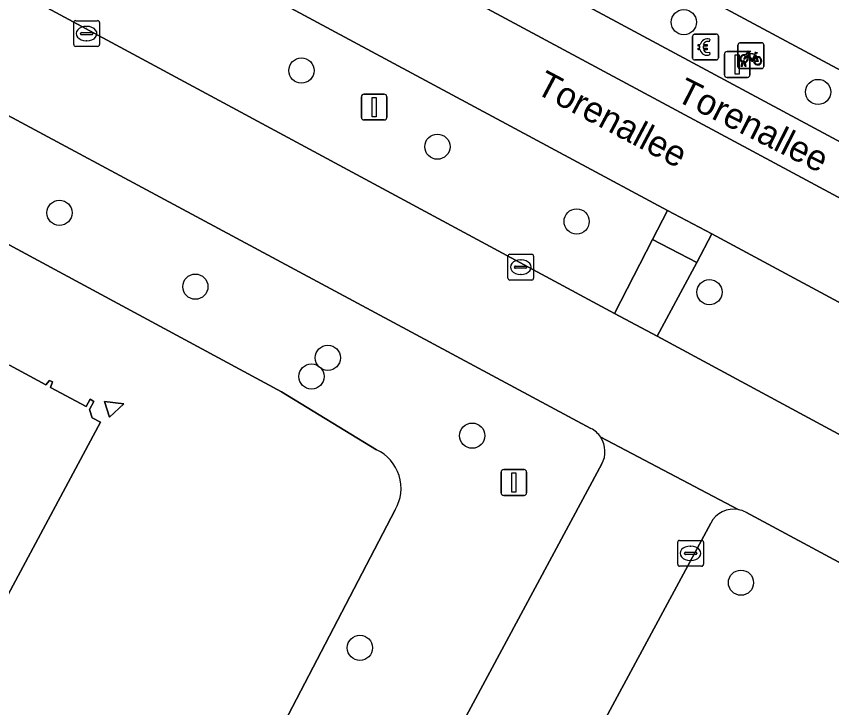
# Model space of a CAD drawing. Extents: x 159489 to 160304, y 383825 to 384531.
# Drawn here: x 159914.43 to 159946.05, y 384116.4 to 384143.23 of the extents above; entities that cross this region are included whole.
import ezdxf

# ---------------------------------------------------------------- set-up
doc = ezdxf.new("R2010")
doc.units = 0
for name, color, linetype in [('IMGEO_Betaalautomaat', 7, 'Continuous'), ('IMGEO_Boom', 7, 'Continuous'), ('IMGEO_Fietsenrek', 7, 'Continuous'), ('IMGEO_Groenvoorziening', 7, 'Continuous'), ('IMGEO_Kolk', 7, 'Continuous'), ('IMGEO_Lichtmast', 7, 'Continuous'), ('IMGEO_Openbare_ruimte_label', 7, 'Continuous'), ('IMGEO_Pand', 7, 'Continuous'), ('IMGEO_Parkeervlak_gesloten', 7, 'Continuous'), ('IMGEO_Rijbaan_lokaal_gesloten', 7, 'Continuous'), ('IMGEO_Voetgangersgebied_gesloten', 7, 'Continuous'), ('IMGEO_Voetpad_gesloten', 7, 'Continuous'), ('IMGEO_Voetpad_open', 7, 'Continuous')]:
    doc.layers.add(name, color=color, linetype=linetype)

msp = doc.modelspace()

# ---------------------------------------------------------------- linework, layer by layer
at = {"layer": 'IMGEO_Betaalautomaat'}
for p, q in [((159940.662, 384141.609), (159940.662, 384142.45)), ((159940.662, 384142.45), (159940.662, 384141.609)), ((159940.737, 384142.533), (159941.578, 384142.533)), ((159941.578, 384142.533), (159940.737, 384142.533)), ((159941.324, 384142.338), (159941.307, 384142.238)), ((159941.661, 384142.459), (159941.661, 384141.618)), ((159941.661, 384141.618), (159941.661, 384142.459)), ((159940.945, 384141.997), (159940.945, 384142.065)), ((159941.066, 384142.065), (159941.066, 384141.997)), ((159941.311, 384141.832), (159941.333, 384141.745)), ((159941.587, 384141.534), (159940.746, 384141.534)), ((159940.746, 384141.534), (159941.587, 384141.534))]:
    msp.add_line(p, q, dxfattribs=at)
for points in [[(159940.945, 384142.065), (159940.876, 384142.065), (159940.876, 384142.134), (159940.955, 384142.134)], [(159940.95, 384141.928), (159940.876, 384141.928), (159940.876, 384141.997), (159940.945, 384141.997)], [(159941.077, 384142.134), (159941.224, 384142.134), (159941.224, 384142.065), (159941.066, 384142.065)], [(159941.066, 384141.997), (159941.224, 384141.997), (159941.224, 384141.928), (159941.08, 384141.928)]]:
    msp.add_lwpolyline(points, dxfattribs=at)
for centre, radius, start, end in [((159940.74, 384142.456), 0.0779, 92.4484, 184.2845), ((159940.74, 384142.456), 0.0779, 92.4484, 184.2845), ((159941.238, 384142.058), 0.293, 73.014, 165.0139), ((159941.584, 384142.456), 0.0779, 2.4484, 94.2845), ((159941.584, 384142.456), 0.0779, 2.4484, 94.2845), ((159941.244, 384142.071), 0.179, 69.3236, 159.5683), ((159941.211, 384141.983), 0.267, 191.8096, 297.0389), ((159941.244, 384141.998), 0.179, 202.7625, 291.8693), ((159940.74, 384141.612), 0.0779, 182.4484, 274.2845), ((159940.74, 384141.612), 0.0779, 182.4484, 274.2845), ((159941.584, 384141.612), 0.0779, 272.4484, 4.2845), ((159941.584, 384141.612), 0.0779, 272.4484, 4.2845)]:
    msp.add_arc(centre, radius, start, end, dxfattribs=at)
at = {"layer": 'IMGEO_Boom'}
for centre in [(159940.319, 384143.002), (159925.488, 384141.122), (159945.528, 384140.293), (159930.762, 384138.168), (159916.103, 384135.603), (159936.162, 384135.269), (159921.375, 384132.738), (159941.314, 384132.524), (159926.512, 384129.976), (159925.878, 384129.253), (159932.113, 384126.957), (159942.536, 384121.253), (159927.757, 384118.726)]:
    msp.add_circle(centre, 0.489, dxfattribs=at)
at = {"layer": 'IMGEO_Fietsenrek'}
for p, q in [((159942.417, 384141.273), (159942.417, 384142.114)), ((159942.417, 384142.114), (159942.417, 384141.273)), ((159942.492, 384142.198), (159943.333, 384142.198)), ((159943.333, 384142.198), (159942.492, 384142.198)), ((159943.417, 384142.123), (159943.417, 384141.282)), ((159943.417, 384141.282), (159943.417, 384142.123)), ((159943.104, 384141.747), (159943.14, 384141.652)), ((159942.544, 384141.282), (159942.583, 384141.442)), ((159942.613, 384141.43), (159942.578, 384141.282)), ((159942.655, 384141.454), (159942.654, 384141.458)), ((159942.696, 384141.282), (159942.662, 384141.424)), ((159942.686, 384141.465), (159942.687, 384141.458)), ((159942.694, 384141.428), (159942.729, 384141.282)), ((159943.342, 384141.198), (159942.501, 384141.198)), ((159942.501, 384141.198), (159943.342, 384141.198)), ((159942.578, 384141.282), (159942.544, 384141.282)), ((159942.729, 384141.282), (159942.696, 384141.282))]:
    msp.add_line(p, q, dxfattribs=at)
for points in [[(159942.751, 384141.672), (159942.699, 384141.582), (159942.659, 384141.557), (159942.66, 384141.604), (159942.715, 384141.698)], [(159942.73, 384141.724), (159942.825, 384141.888), (159942.911, 384141.874), (159942.913, 384141.865), (159942.857, 384141.854), (159942.83, 384141.809), (159943.086, 384141.768)], [(159943.026, 384141.48), (159942.976, 384141.48), (159942.785, 384141.731), (159942.766, 384141.699)], [(159943.073, 384141.743), (159942.816, 384141.784), (159942.799, 384141.755), (159942.966, 384141.535), (159943.073, 384141.743)], [(159943.121, 384141.645), (159943.091, 384141.722), (159942.982, 384141.504), (159943.025, 384141.504)], [(159943.086, 384141.768), (159943.111, 384141.817), (159943.105, 384141.821), (159943.082, 384141.825), (159943.07, 384141.832), (159943.069, 384141.835), (159943.071, 384141.84), (159943.166, 384141.825), (159943.168, 384141.815), (159943.158, 384141.802), (159943.146, 384141.796), (159943.132, 384141.802), (159943.104, 384141.747)], [(159943.055, 384141.504), (159943.175, 384141.503), (159943.131, 384141.617)], [(159943.151, 384141.624), (159943.206, 384141.479), (159943.056, 384141.479)]]:
    msp.add_lwpolyline(points, dxfattribs=at)
for centre, radius, start, end in [((159942.495, 384142.12), 0.0779, 92.4484, 184.2845), ((159942.495, 384142.12), 0.0779, 92.4484, 184.2845), ((159943.339, 384142.12), 0.0779, 2.4484, 94.2845), ((159943.339, 384142.12), 0.0779, 2.4484, 94.2845), ((159942.657, 384141.583), 0.159, 62.6766, 242.1369), ((159942.657, 384141.583), 0.129, 63.3192, 238.903), ((159942.657, 384141.583), 0.129, 283.6043, 43.4302), ((159942.657, 384141.583), 0.159, 283.5766, 46.6042), ((159942.637, 384141.454), 0.0499, 12.8025, 158.6934), ((159942.657, 384141.583), 0.159, 253.9967, 271.7867), ((159942.637, 384141.454), 0.0174, 12.8025, 163.4502), ((159942.657, 384141.583), 0.129, 253.415, 269.0204), ((159943.184, 384141.499), 0.159, 113.3408, 178.3217), ((159943.184, 384141.499), 0.159, 187.0065, 105.7708), ((159943.184, 384141.499), 0.129, 113.923, 177.9556), ((159943.184, 384141.499), 0.129, 188.6715, 104.5883), ((159942.495, 384141.276), 0.0779, 182.4484, 274.2845), ((159942.495, 384141.276), 0.0779, 182.4484, 274.2845), ((159943.339, 384141.276), 0.0779, 272.4484, 4.2845), ((159943.339, 384141.276), 0.0779, 272.4484, 4.2845)]:
    msp.add_arc(centre, radius, start, end, dxfattribs=at)
at = {"layer": 'IMGEO_Groenvoorziening'}
for points in [[(159899.78, 384152.109), (159937.631, 384131.692), (159939.104, 384134.563), (159939.687, 384135.699), (159936.03, 384137.66), (159905.423, 384154.113)], [(159936.719, 384127.237), (159897.901, 384148.099)], [(159894.916, 384142.599), (159901.414, 384139.029), (159901.585, 384139.321), (159903.655, 384138.186), (159904.538, 384139.549), (159924.712, 384128.658), (159928.404, 384126.412)], [(159948.486, 384130.974), (159941.411, 384134.785), (159940.822, 384133.676), (159939.285, 384130.812), (159961.784, 384118.678)], [(159922.54, 384098.71), (159937.141, 384125.859)], [(159929.13, 384124.085), (159916.853, 384100.528), (159917.244, 384100.323), (159918.413, 384099.707), (159921.145, 384098.268)], [(159991.605, 384097.15), (159989.51, 384098.309), (159987.628, 384099.386), (159982.455, 384102.271), (159982.609, 384102.542), (159962.154, 384113.541), (159959.747, 384109.085), (159959.992, 384108.923), (159958.681, 384106.439), (159961.293, 384104.909), (159955.461, 384093.87), (159949.317, 384097.048), (159955.08, 384108.246), (159958.162, 384106.791), (159959.019, 384108.407), (159958.777, 384108.556), (159961.579, 384113.852), (159942.73, 384123.985)], [(159941.364, 384123.56), (159925.758, 384094.623), (159925.487, 384093.814), (159920.135, 384063.9), (159960.274, 384047.972)]]:
    msp.add_lwpolyline(points, dxfattribs=at)
for centre, radius, start, end in [((159936.259, 384126.352), 0.997, 32.8489, 62.5434), ((159936.254, 384126.339), 1.008, 331.5653, 33.308), ((159927.691, 384124.913), 1.66, 330.0783, 64.5764), ((159942.254, 384123.11), 0.997, 79.6518, 153.1777), ((159942.258, 384123.13), 0.976, 61.0658, 79.651)]:
    msp.add_arc(centre, radius, start, end, dxfattribs=at)
at = {"layer": 'IMGEO_Kolk'}
for p, q in [((159916.657, 384142.132), (159916.657, 384142.984)), ((159916.732, 384143.058), (159917.584, 384143.058)), ((159917.658, 384142.984), (159917.658, 384142.132)), ((159917.145, 384142.838), (159917.17, 384142.838)), ((159916.916, 384142.552), (159916.916, 384142.564)), ((159917.354, 384142.515), (159916.956, 384142.515)), ((159916.959, 384142.601), (159917.357, 384142.601)), ((159917.4, 384142.564), (159917.4, 384142.552)), ((159917.584, 384142.058), (159916.732, 384142.058)), ((159917.168, 384142.278), (159917.143, 384142.278)), ((159933.494, 384133.07), (159933.494, 384133.922)), ((159933.569, 384133.996), (159934.421, 384133.996)), ((159933.982, 384133.776), (159934.007, 384133.776)), ((159934.495, 384133.922), (159934.495, 384133.07)), ((159933.753, 384133.49), (159933.753, 384133.502)), ((159934.191, 384133.453), (159933.793, 384133.453)), ((159933.796, 384133.539), (159934.194, 384133.539)), ((159934.237, 384133.502), (159934.237, 384133.49)), ((159934.005, 384133.216), (159933.98, 384133.216)), ((159934.421, 384132.996), (159933.569, 384132.996)), ((159940.083, 384121.967), (159940.083, 384122.819)), ((159940.158, 384122.893), (159941.01, 384122.893)), ((159941.084, 384122.819), (159941.084, 384121.967)), ((159940.342, 384122.387), (159940.342, 384122.399)), ((159940.385, 384122.436), (159940.783, 384122.436)), ((159940.571, 384122.673), (159940.596, 384122.673)), ((159940.826, 384122.399), (159940.826, 384122.387)), ((159940.78, 384122.35), (159940.382, 384122.35)), ((159940.594, 384122.113), (159940.569, 384122.113)), ((159941.01, 384121.893), (159940.158, 384121.893))]:
    msp.add_line(p, q, dxfattribs=at)
for points in [[(159916.657, 384142.132), (159916.657, 384142.984)], [(159916.732, 384143.058), (159917.584, 384143.058)], [(159917.658, 384142.984), (159917.658, 384142.132)], [(159917.584, 384142.058), (159916.732, 384142.058)], [(159933.494, 384133.07), (159933.494, 384133.922)], [(159933.569, 384133.996), (159934.421, 384133.996)], [(159934.495, 384133.922), (159934.495, 384133.07)], [(159934.421, 384132.996), (159933.569, 384132.996)], [(159940.083, 384121.967), (159940.083, 384122.819)], [(159940.158, 384122.893), (159941.01, 384122.893)], [(159941.084, 384122.819), (159941.084, 384121.967)], [(159941.01, 384121.893), (159940.158, 384121.893)]]:
    msp.add_lwpolyline(points, dxfattribs=at)
for centre, radius, start, end in [((159916.734, 384142.982), 0.0765, 91.552, 178.448), ((159916.734, 384142.982), 0.0765, 91.552, 178.448), ((159917.582, 384142.982), 0.0765, 1.552, 88.448), ((159917.582, 384142.982), 0.0765, 1.552, 88.448), ((159916.956, 384142.561), 0.0403, 85.8775, 175.7526), ((159916.953, 384142.551), 0.0366, 178.938, 274.7102), ((159917.357, 384142.558), 0.043, 264.8664, 352.4533), ((159917.361, 384142.563), 0.0386, 1.7309, 96.639), ((159916.734, 384142.134), 0.0765, 181.552, 268.448), ((159916.734, 384142.134), 0.0765, 181.552, 268.448), ((159917.582, 384142.134), 0.0765, 271.552, 358.448), ((159917.582, 384142.134), 0.0765, 271.552, 358.448), ((159933.571, 384133.92), 0.0765, 91.552, 178.448), ((159933.571, 384133.92), 0.0765, 91.552, 178.448), ((159934.419, 384133.92), 0.0765, 1.552, 88.448), ((159934.419, 384133.92), 0.0765, 1.552, 88.448), ((159933.793, 384133.499), 0.0403, 85.8775, 175.7526), ((159933.79, 384133.489), 0.0366, 178.938, 274.7102), ((159934.194, 384133.496), 0.043, 264.8664, 352.4533), ((159934.198, 384133.501), 0.0386, 1.7309, 96.639), ((159933.571, 384133.072), 0.0765, 181.552, 268.448), ((159933.571, 384133.072), 0.0765, 181.552, 268.448), ((159934.419, 384133.072), 0.0765, 271.552, 358.448), ((159934.419, 384133.072), 0.0765, 271.552, 358.448), ((159940.16, 384122.817), 0.0765, 91.552, 178.448), ((159940.16, 384122.817), 0.0765, 91.552, 178.448), ((159941.008, 384122.817), 0.0765, 1.552, 88.448), ((159941.008, 384122.817), 0.0765, 1.552, 88.448), ((159940.382, 384122.396), 0.0403, 85.8775, 175.7526), ((159940.379, 384122.386), 0.0366, 178.938, 274.7102), ((159940.783, 384122.393), 0.043, 264.8664, 352.4533), ((159940.787, 384122.398), 0.0386, 1.7309, 96.639), ((159940.16, 384121.969), 0.0765, 181.552, 268.448), ((159940.16, 384121.969), 0.0765, 181.552, 268.448), ((159941.008, 384121.969), 0.0765, 271.552, 358.448), ((159941.008, 384121.969), 0.0765, 271.552, 358.448)]:
    msp.add_arc(centre, radius, start, end, dxfattribs=at)
for centre, major_axis, ratio, start_param, end_param in [((159917.144, 384142.558), (-0.387, 0.002), 0.722429, 4.712389, 7.853982), ((159917.169, 384142.558), (-0.39, 0.002), 0.717154, 1.570796, 4.712389), ((159933.981, 384133.496), (-0.387, 0.002), 0.722429, 4.712389, 7.853982), ((159934.006, 384133.496), (-0.39, 0.002), 0.717154, 1.570796, 4.712389), ((159940.57, 384122.393), (-0.387, 0.002), 0.722429, 4.712389, 7.853982), ((159940.595, 384122.393), (-0.39, 0.002), 0.717154, 1.570796, 4.712389)]:
    msp.add_ellipse(centre, major_axis=major_axis, ratio=ratio, start_param=start_param, end_param=end_param, dxfattribs=at)
at = {"layer": 'IMGEO_Lichtmast'}
for p, q in [((159941.896, 384140.958), (159941.896, 384141.758)), ((159941.896, 384141.758), (159941.896, 384140.958)), ((159941.996, 384141.858), (159942.786, 384141.858)), ((159942.786, 384141.858), (159941.996, 384141.858)), ((159942.886, 384141.758), (159942.886, 384140.958)), ((159942.886, 384140.958), (159942.886, 384141.758)), ((159942.786, 384140.858), (159941.996, 384140.858)), ((159941.996, 384140.858), (159942.786, 384140.858)), ((159927.812, 384139.305), (159927.812, 384140.105)), ((159927.812, 384140.105), (159927.812, 384139.305)), ((159927.912, 384140.205), (159928.702, 384140.205)), ((159928.702, 384140.205), (159927.912, 384140.205)), ((159928.802, 384140.105), (159928.802, 384139.305)), ((159928.802, 384139.305), (159928.802, 384140.105)), ((159928.702, 384139.205), (159927.912, 384139.205)), ((159927.912, 384139.205), (159928.702, 384139.205)), ((159933.233, 384124.741), (159933.233, 384125.541)), ((159933.233, 384125.541), (159933.233, 384124.741)), ((159933.333, 384125.641), (159934.123, 384125.641)), ((159934.123, 384125.641), (159933.333, 384125.641)), ((159934.223, 384125.541), (159934.223, 384124.741)), ((159934.223, 384124.741), (159934.223, 384125.541)), ((159934.123, 384124.641), (159933.333, 384124.641)), ((159933.333, 384124.641), (159934.123, 384124.641))]:
    msp.add_line(p, q, dxfattribs=at)
for points in [[(159942.316, 384141.733), (159942.466, 384141.733), (159942.466, 384140.983), (159942.316, 384140.983), (159942.316, 384141.733)], [(159928.232, 384140.08), (159928.382, 384140.08), (159928.382, 384139.33), (159928.232, 384139.33), (159928.232, 384140.08)], [(159933.653, 384125.516), (159933.803, 384125.516), (159933.803, 384124.766), (159933.653, 384124.766), (159933.653, 384125.516)]]:
    msp.add_lwpolyline(points, dxfattribs=at)
for centre, start, end in [((159941.996, 384141.758), 90, 180), ((159941.996, 384141.758), 90, 180), ((159942.786, 384141.758), 0, 90), ((159942.786, 384141.758), 360, 90), ((159941.996, 384140.958), 180, 270), ((159941.996, 384140.958), 180, 270), ((159942.786, 384140.958), 270, 0), ((159942.786, 384140.958), 270, 0), ((159927.912, 384140.105), 90, 180), ((159927.912, 384140.105), 90, 180), ((159928.702, 384140.105), 0, 90), ((159928.702, 384140.105), 360, 90), ((159927.912, 384139.305), 180, 270), ((159927.912, 384139.305), 180, 270), ((159928.702, 384139.305), 270, 0), ((159928.702, 384139.305), 270, 0), ((159933.333, 384125.541), 90, 180), ((159933.333, 384125.541), 90, 180), ((159934.123, 384125.541), 0, 90), ((159934.123, 384125.541), 360, 90), ((159933.333, 384124.741), 180, 270), ((159933.333, 384124.741), 180, 270), ((159934.123, 384124.741), 270, 0), ((159934.123, 384124.741), 270, 0)]:
    msp.add_arc(centre, 0.1, start, end, dxfattribs=at)
at = {"layer": 'IMGEO_Pand'}
msp.add_lwpolyline([(159900.73, 384095.84), (159917.69, 384127.479), (159917.369, 384127.65), (159917.269, 384127.969), (159917.44, 384128.289), (159917.29, 384128.369), (159917.14, 384128.09), (159915.76, 384128.83), (159915.829, 384129.049), (159915.72, 384129.099), (159915.579, 384128.929), (159914.17, 384129.69)], dxfattribs=at)
msp.add_lwpolyline([(159918.6, 384128.19), (159917.85, 384128.289), (159918.04, 384127.679)], close=True, dxfattribs=at)
at = {"layer": 'IMGEO_Parkeervlak_gesloten'}
msp.add_lwpolyline([(159912.004, 384156.822), (159911.095, 384155.132), (159969.104, 384123.965), (159970.012, 384125.655)], close=True, dxfattribs=at)
at = {"layer": 'IMGEO_Rijbaan_lokaal_gesloten'}
msp.add_lwpolyline([(159910.698, 384167.182), (159905.438, 384169.984), (159900.602, 384172.559), (159897.742, 384167.217), (159991.549, 384116.926), (159998.32, 384113.209), (160001.178, 384118.557)], close=True, dxfattribs=at)
msp.add_lwpolyline([(159997.184, 384111.056), (159989.868, 384114.987), (159988.96, 384113.296), (159974.025, 384121.32), (159974.934, 384123.011), (159970.012, 384125.655), (159969.104, 384123.965), (159911.095, 384155.132), (159912.004, 384156.822), (159894.341, 384166.312), (159891.699, 384161.454), (159893.509, 384160.525), (159895.723, 384159.334), (159901.046, 384156.469), (159905.423, 384154.113), (159936.03, 384137.66), (159939.687, 384135.699), (159941.411, 384134.785), (159948.486, 384130.974), (159966.662, 384121.216), (159972.01, 384118.346), (159992.857, 384107.129)], dxfattribs=at)
at = {"layer": 'IMGEO_Voetgangersgebied_gesloten'}
for points in [[(159892.737, 384155.882), (159889.629, 384157.595), (159887.537, 384153.695), (159890.072, 384152.355), (159891.089, 384151.818), (159892.538, 384151.052), (159897.901, 384148.099), (159936.719, 384127.237)], [(159939.285, 384130.812), (159937.631, 384131.692), (159899.78, 384152.109)], [(159961.784, 384118.678), (159939.285, 384130.812)], [(159937.097, 384126.893), (159942.433, 384124.091)], [(159942.433, 384124.091), (159937.097, 384126.893)], [(159937.141, 384125.859), (159922.54, 384098.71)], [(159942.73, 384123.985), (159961.579, 384113.852), (159962.154, 384113.541), (159982.609, 384102.542), (159982.455, 384102.271), (159987.628, 384099.386), (159989.51, 384098.309), (159991.605, 384097.15), (159991.945, 384097.77), (159993.361, 384100.352), (159992.484, 384100.869), (159992.05, 384101.215), (159992.519, 384102.091), (159987.632, 384104.854), (159985.203, 384106.114), (159968.335, 384115.191)], [(159909.959, 384072.229), (159906.352, 384074.165), (159905.689, 384074.538), (159903.921, 384075.532), (159902.893, 384073.618), (159902.185, 384072.3), (159911.385, 384067.372), (159920.135, 384063.9), (159925.487, 384093.814), (159925.758, 384094.623), (159941.364, 384123.56)]]:
    msp.add_lwpolyline(points, dxfattribs=at)
for centre, radius, start, end in [((159936.259, 384126.352), 0.997, 32.8489, 62.5434), ((159936.254, 384126.339), 1.008, 331.5653, 33.308), ((159942.254, 384123.11), 0.997, 79.6518, 153.1777), ((159942.258, 384123.13), 0.976, 61.0658, 79.651)]:
    msp.add_arc(centre, radius, start, end, dxfattribs=at)
at = {"layer": 'IMGEO_Voetpad_gesloten'}
msp.add_lwpolyline([(159940.822, 384133.676), (159941.411, 384134.785), (159939.687, 384135.699), (159939.104, 384134.563)], close=True, dxfattribs=at)
at = {"layer": 'IMGEO_Voetpad_open'}
for points in [[(159993.803, 384125.855), (159988.602, 384128.644), (159972.877, 384137.075), (159970.476, 384138.363), (159951.365, 384148.61), (159948.39, 384150.205), (159940.225, 384154.583), (159935.251, 384157.25), (159918.126, 384166.432), (159912.035, 384169.676), (159906.775, 384172.478), (159901.96, 384175.043), (159901.938, 384175.054), (159899.663, 384176.232), (159894.932, 384167.392), (159894.341, 384166.312), (159912.004, 384156.822), (159970.012, 384125.655), (159974.934, 384123.011), (159989.868, 384114.987), (159997.184, 384111.056)], [(159998.32, 384113.209), (159991.549, 384116.926), (159897.742, 384167.217), (159900.602, 384172.559), (159905.438, 384169.984), (159910.698, 384167.182), (160001.178, 384118.557)], [(159928.404, 384126.412), (159924.712, 384128.658), (159904.538, 384139.549), (159903.655, 384138.186), (159901.585, 384139.321), (159901.414, 384139.029), (159894.916, 384142.599)], [(159914.17, 384129.69), (159915.579, 384128.929), (159915.72, 384129.099), (159915.829, 384129.049), (159915.76, 384128.83), (159917.14, 384128.09), (159917.29, 384128.369), (159917.44, 384128.289), (159917.269, 384127.969), (159917.369, 384127.65), (159917.69, 384127.479), (159900.73, 384095.84)], [(159916.853, 384100.528), (159929.13, 384124.085)]]:
    msp.add_lwpolyline(points, dxfattribs=at)
for points in [[(159940.822, 384133.676), (159939.104, 384134.563), (159937.631, 384131.692), (159939.285, 384130.812)], [(159918.04, 384127.679), (159917.85, 384128.289), (159918.6, 384128.19)]]:
    msp.add_lwpolyline(points, close=True, dxfattribs=at)
msp.add_arc((159927.691, 384124.913), 1.66, 330.0783, 64.5764, dxfattribs=at)

# ---------------------------------------------------------------- texts
at = {"layer": 'IMGEO_Openbare_ruimte_label'}
for rotation, p in [(332.1027, (159934.517, 384140.275)), (333.2044, (159939.962, 384139.983))]:
    msp.add_text('Torenallee', height=1, rotation=rotation, dxfattribs=at).set_placement(p)

doc.saveas('drawing.dxf')
